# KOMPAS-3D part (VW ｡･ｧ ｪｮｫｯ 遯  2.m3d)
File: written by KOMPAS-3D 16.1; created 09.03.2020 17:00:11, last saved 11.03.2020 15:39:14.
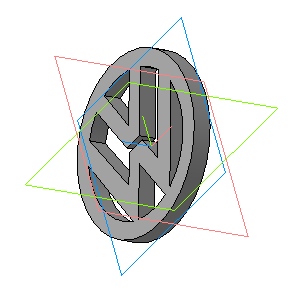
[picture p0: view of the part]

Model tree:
1. Эскиз:1
2. Операция выдавливания:1
     Расстояние 1 = 5.3
3. Эскиз:3
4. Вырезать элемент выдавливания:1
     Расстояние 1 = 5.3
